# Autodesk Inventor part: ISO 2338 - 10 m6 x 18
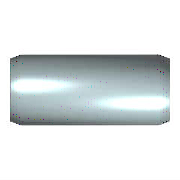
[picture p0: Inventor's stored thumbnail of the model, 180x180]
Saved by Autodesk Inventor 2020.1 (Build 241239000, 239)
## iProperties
Created: 2019-01
Part Number: ISO 2338 - 10 m6 x 18
Material: Edelstahl, austenitisch
Description: Zylinderstift
Document SubType Name: Modeling
Standard: ISO 2338
Designer: lutzd
Standard Revision: Second edition 1997-11-01
Standards Organization: ISO
Language: de-DE
Size Designation: 10 m6 x 18
Categories: <MemberInstance><Categories><Category DisplayName="Verbindungselemente" InternalName="e4da775c-781d-43d5-af7c-5136215cf5a6" Mnemonic="FSTN"><Category DisplayNam
Mass: 11.05 g
Surface Area: 6.8816 cm^2
Volume: 1.38125 cm^3
Density: 8 g/cm^3
Appearance: Halbpoliert
IsCustomPart: 0
Author: lutzd
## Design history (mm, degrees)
sketch "Skizze"
  geometry: C1 r 5 at (0, 0); 1 further point
  constraints: 1 centre point, 1 coincident
  dimensions: "d1" = 10 diameter of C1 (= NND)
extrude "Körper" new body sketch "Skizze" distance "d2" = 18 (= NLG); taper "d3" = 0 deg
chamfer "Skizze2" distance "d8" = 2 (= PHH); stored, may be unused: angle "d9" = 15 deg (= FAWI), second distance "d12" = 2 (= PHH)
body "Solid1"
chamfer "Fase1" distance "d4" = 2 (= PHH); stored, may be unused: angle "d5" = 15 deg (= FAWI), second distance "d11" = 2 (= PHH)
other parameters: "NND" = 10 [user parameter; used in 1 equation term], "NLG" = 18 [user parameter; used in 1 equation term], "PHH" = 2 [user parameter; used in 4 equation terms], "FAWI" = 15 deg [user parameter; used in 2 equation terms], "d13" = 0, "d15" = 0, "d16" = 0, "KAH" = 0 [user parameter]
